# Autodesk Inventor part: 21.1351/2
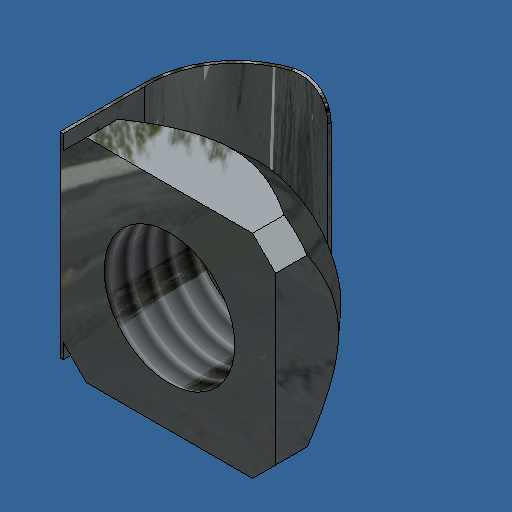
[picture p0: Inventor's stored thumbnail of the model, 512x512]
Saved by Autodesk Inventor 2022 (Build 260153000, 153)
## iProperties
Created: 2006-12
Part Number: 21.1351/2
Document SubType Name: Modeling
Designer: Andy Moles
Material: Steel, Mild
Density: 7.85 g/cm^3
Mass: 4.24899 g
Surface Area: 8.34272 cm^2
Volume: 0.541273 cm^3
Description: M8 SQUARE NUT POS FXG
Vendor: S
Appearance: Zinc
Title: M8 SQUARE NUT POS FXG
Author: Andy Moles
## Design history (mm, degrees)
sketch "Sketch2"
  geometry: L1 (-5.086, -6.5)-(5.086, -6.5); L2 (6.5, -5.086)-(6.5, 5.086); L3 (5.086, 6.5)-(-5.086, 6.5); L4 (-6.5, 5.086)-(-6.5, -5.086); L5 (-6.5, 6.5)-(6.5, -6.5); L6 (5.086, 6.5)-(6.5, 5.086); L7 (0, -6.5)-(0, 6.5); L8 (-6.5, 0)-(6.5, 0); L9 (-5.086, 6.5)-(-6.5, 5.086); L10 (-5.086, -6.5)-(-6.5, -5.086); L11 (5.086, -6.5)-(6.5, -5.086); C1 r 4 at (0, 0); 2 further points
  constraints: 22 end point, 6 symmetric about line, 4 parallel, 3 midpoint, 2 coincident, 2 perpendicular, 1 centre point, 1 horizontal
  dimensions: "THREAD" = 8 diameter of C1; "d3" = 45 deg angle of L3 L6 (derived); "d4" = 2 distance of L3.start L2.end
extrude "Extrusion1" new body sketch "Sketch2" distance "d5" = 5.5; taper "d6" = 0 deg
workplane "Work Plane1"
sketch "Sketch4"
  geometry: L1 (12.192, 0)-(4.192, 0) reference; L2 (8.192, 0)-(13.192, 0); L3 (16.385, 5.5)-(16.385, 3.5); L4 (13.192, 0)-(16.797, 3.952); L5 (13.192, 0)-(16.385, 0); L6 (16.385, 3.5)-(16.385, 0); L7 (16.797, 3.952)-(16.797, -0.412); L8 (16.797, -0.412)-(13.192, -0.412); L9 (13.192, -0.412)-(13.192, 0); L10 (8.192, 5.5)-(8.192, 0); L11 (16.385, 5.5)-(16.385, 0) reference; L12 (16.385, 3.5)-(17.502, 3.5); L13 (9.192, 5.5)-(16.385, 5.5) reference
  constraints: 20 end point, 6 perpendicular, 1 collinear, 1 midpoint, 1 parallel, 1 point on line
  dimensions: "d10" = 5 distance of L2.start L2.end; "d15" = 2 distance between parallel lines of L12 L13
revolve "Revolution1" sketch "Sketch4" stored, may be unused: angle "d12" = 90 deg
thread "Thread1" dims "d13" = 10, "d14" = 0
sketch "Sketch6"
  geometry: L1 (2.954, -2.535)-(2.954, 6.006); L2 (2.954, -2.535)-(2.954, -7.535); L3 (2.954, -2.535)-(3.154, -2.535); L4 (3.154, -2.535)-(3.154, -7.535); L5 (-2.646, -13.135)-(-2.646, -13.335); L6 (2.954, 0)-(2.954, -1.933); L7 (-8.632, -2.535)-(1.539, -2.535) reference; L8 (2.954, -2.535)-(2.954, -4.468) reference; A1 r 5.374 centre (-2.416, -7.766) between (-2.646, -13.135) and (2.954, -7.535); A2 r 5.574 centre (-2.416, -7.766) between (-2.646, -13.335) and (3.154, -7.535); 4 further points; 1 other entity
  constraints: 12 end point, 4 point on circle, 3 collinear, 2 centre point, 2 horizontal, 2 parallel, 2 perpendicular, 1 coincident, 3 other
  dimensions: "d25" = 5 distance of L1.start L2.end; "d23" = 0.2 distance of L1.start L3.end; "d22" = 0.2 distance of L5.start L5.end; "d21" = 10.8 distance from line of L5.end L3; "d24" = 5.37434 radius of A1
extrude "Extrusion3" join sketch "Sketch6" taper "d27" = 0 deg; stored distance "d28" = 12
fillet "Fillet2" dims "d29" = 2
body "Solid1"
